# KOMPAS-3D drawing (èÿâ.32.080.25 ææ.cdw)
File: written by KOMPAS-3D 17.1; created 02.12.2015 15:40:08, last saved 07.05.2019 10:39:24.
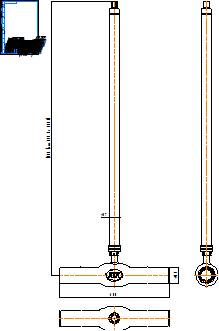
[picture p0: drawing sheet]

Sheet 1: A4, portrait

Title block, sheet 1: name: КШГ.32.080.25 СС; material: Внимание! Данный продукт является объектом авторского права ООО «Торговый Дом АДЛ». / Запрещается изменение, копирование, распространение / (в том числе путем копирования на другие сайты и ресурсы в Интернете) / или любое иное использование информации и объектов без предварительного / согласия правообладателя (ООО «Торговый Дом АДЛ»).; sheets: 1; organisation: ООО "Торговый дом АДЛ"; sheet format: A4; stored path: C:\Users\kka\KOMPAS_Work\Модели кранов для исследований\DN50\С удлинением\КШГ.32.050.40 СС ГЧ _ Шаровой кран БИВАЛ Ду50 Ру4 МПа редуцированный под приварку, с удлинением штока H=1100.cdw; drawn by: Климкович К.А.; drawn by, date: 02.12.15

Views: Вид 1, Проекционный вид 2, Проекционный вид 3
Referenced files in C:\Users\kka\KOMPAS_Work\Модели кранов для исследований\DN80\С удлинением\: КШТ.22.080.25 СС.a3d, КШГ.35.065.25 СС.a3d!КШГ.45.065.10 СС!Деталь (локальная).m3d
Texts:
  Klimkovich
  ADL
  (от 297 до 5000)
Dimensions and other numbers on the sheet: 600; 1500; 89; 57; 1:1; 1; 02.12.15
